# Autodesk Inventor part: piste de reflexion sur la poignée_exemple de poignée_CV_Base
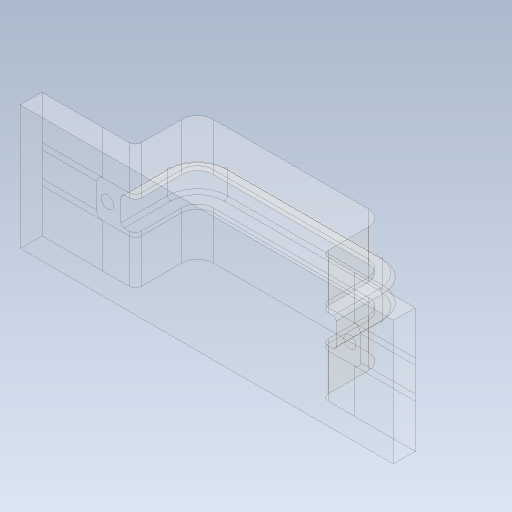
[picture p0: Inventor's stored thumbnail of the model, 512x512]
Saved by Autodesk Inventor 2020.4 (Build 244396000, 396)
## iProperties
Created: 2021-10
Part Number: piste de reflexion sur la poignée_exemple de poignée_CV_Base
Material: Générique
Document SubType Name: Modeling
Designer: mel
Density: 1 g/cm^3
Appearance: Par défaut
Author: mel
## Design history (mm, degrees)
node "piste de reflexion sur la poignée_exemple de poignée_MP"
feature "Solide4::piste de reflexion sur la poignée_exemple de poigné"
tag "FonctionRepérage1"
node "Solide1"
feature "piste de reflexion sur la poignée_exemple de poignée_MP_Corp"
